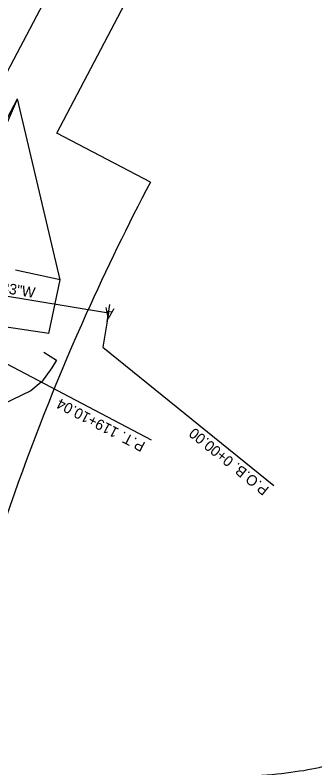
# Model space of a CAD drawing. Extents: x 674098 to 689971, y 764717 to 781049.
# Drawn here: x 688948.3 to 689118.6, y 766697.2 to 767125.1 of the extents above; entities that cross this region are included whole.
import ezdxf

# ---------------------------------------------------------------- set-up
doc = ezdxf.new("R2010")
doc.units = 0
for name, color, linetype in [('FLOODPLAIN', 7, 'Continuous'), ('R_Horz Alg', 7, 'Continuous'), ('R_Horz Alg Annot', 7, 'Continuous'), ('R_Horz Alg Station', 7, 'Continuous'), ('R_Horz Alg Station Annot', 7, 'Continuous'), ('R_Proposed Const Limits Stage 2', 7, 'Continuous'), ('R_Proposed Road S2', 7, 'Continuous'), ('R_Proposed Shoulder S2', 7, 'Continuous'), ('S_EXIST_ROW', 7, 'Continuous')]:
    doc.layers.add(name, color=color, linetype=linetype)

msp = doc.modelspace()

# ---------------------------------------------------------------- linework, layer by layer
at = {"layer": 'FLOODPLAIN'}
msp.add_open_spline([(688557.23, 766766.05), (688591.58, 766711.04), (688595.35, 766687.04), (688608.48, 766656.15), (688627.02, 766628.3), (688632.82, 766586.19), (688639.4, 766524.53), (688653.57, 766501.98), (688669.3, 766485), (688687.59, 766474.45), (688723.13, 766481.9), (688739.6, 766509.51), (688789, 766687.63), (688806.98, 766729.19), (688822.47, 766746.61), (688835.88, 766751.3), (688842.63, 766741.88), (688846.4, 766712.12), (688847.97, 766698.77), (688859.62, 766686.41), (688884.96, 766674.2), (688946.59, 766675.74), (689003.92, 766689.73), (689113.2, 766693.11), (689155.64, 766709.56), (689222.69, 766748.31), (689278.94, 766804.47), (689325.37, 766856.38), (689397.34, 766962.93), (689435.45, 766991.81), (689488.41, 767032.29), (689550.62, 767060.41), (689676.67, 767118.63), (689783.6, 767157.05), (689856.65, 767174.65), (689971.45, 767193.2)], degree=2, dxfattribs=at)
at = {"layer": 'R_Horz Alg'}
for p, q in [((688875.39, 766962.69), (689080.13, 767352.11)), ((689001.37, 766955.64), (688881.98, 766975.21))]:
    msp.add_line(p, q, dxfattribs=at)
at = {"layer": 'R_Horz Alg Station'}
for points in [[(688875.39, 766962.69), (689025.58, 766883.72)], [(689000.56, 766950.71), (689002.18, 766960.58)], [(689001.37, 766955.64), (688998.19, 766936.26), (689095.23, 766857.68)]]:
    msp.add_lwpolyline(points, dxfattribs=at)
at = {"layer": 'R_Proposed Const Limits Stage 2'}
msp.add_line((688973.98, 766974.56), (688949.64, 767077.46), dxfattribs=at)
msp.add_lwpolyline([(688964.61, 766933.45), (688971.86, 766928.87), (688969.15, 766924.65), (688963.21, 766916.51), (688963.19, 766916.49), (688957.31, 766911.58), (688941.2, 766903.78), (688934.78, 766899.47), (688916.53, 766875.79), (688912.2, 766869.83), (688905.96, 766860.8), (688904.46, 766857.46), (688896.27, 766813.43), (688894.91, 766806.62), (688888.63, 766776), (688887.87, 766770.9), (688882.72, 766734.86), (688881.93, 766728.74), (688876.21, 766683.7)], dxfattribs=at)
at = {"layer": 'R_Proposed Road S2'}
for p, q in [((688902.83, 766989.09), (688949.64, 767077.46)), ((688973.98, 766974.56), (688948.51, 766980.15)), ((688967.45, 766944.12), (688973.98, 766974.56)), ((688967.45, 766944.12), (688914.58, 766952))]:
    msp.add_line(p, q, dxfattribs=at)
at = {"layer": 'R_Proposed Shoulder S2'}
msp.add_line((688920.9, 767010.83), (688949.64, 767077.46), dxfattribs=at)
at = {"layer": 'S_EXIST_ROW'}
for p, q in [((688972.02, 767058.04), (689272.78, 767630.13)), ((689025.13, 767030.12), (688972.02, 767058.04))]:
    msp.add_line(p, q, dxfattribs=at)
for start, end in [(152.26789, 155.84367), (155.84367, 165.34172)]:
    msp.add_arc((690204.47, 766410.11), 1332.39, start, end, dxfattribs=at)

# ---------------------------------------------------------------- texts
at = {"layer": 'R_Horz Alg'}
msp.add_text('A', height=6, rotation=170.6924, dxfattribs=at).set_placement((689004.82, 766958.12))
at = {"layer": 'R_Horz Alg Annot'}
msp.add_text('N80%%d41\'33"W', height=6, rotation=350.6924, dxfattribs=at).set_placement((688912.05, 766971.98))
at = {"layer": 'R_Horz Alg Station Annot'}
for s, rotation, p in [('P.T. 119+10.04', 152.2665, (689022.71, 766881.86)), ('P.O.B. 0+00.00', 140.9974, (689092.99, 766856.25))]:
    msp.add_text(s, height=6, rotation=rotation, dxfattribs=at).set_placement(p)

doc.saveas('drawing.dxf')
